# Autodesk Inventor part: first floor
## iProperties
Created: 2018-12
Part Number: first floor
Document SubType Name: Modeling
Designer: Harindersingh
Density: 1 g/cm^3
Author: Harindersingh
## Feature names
1. Extrusion1
2. Extrusion2
3. Extrusion3
4. Extrusion4
5. Extrusion5
